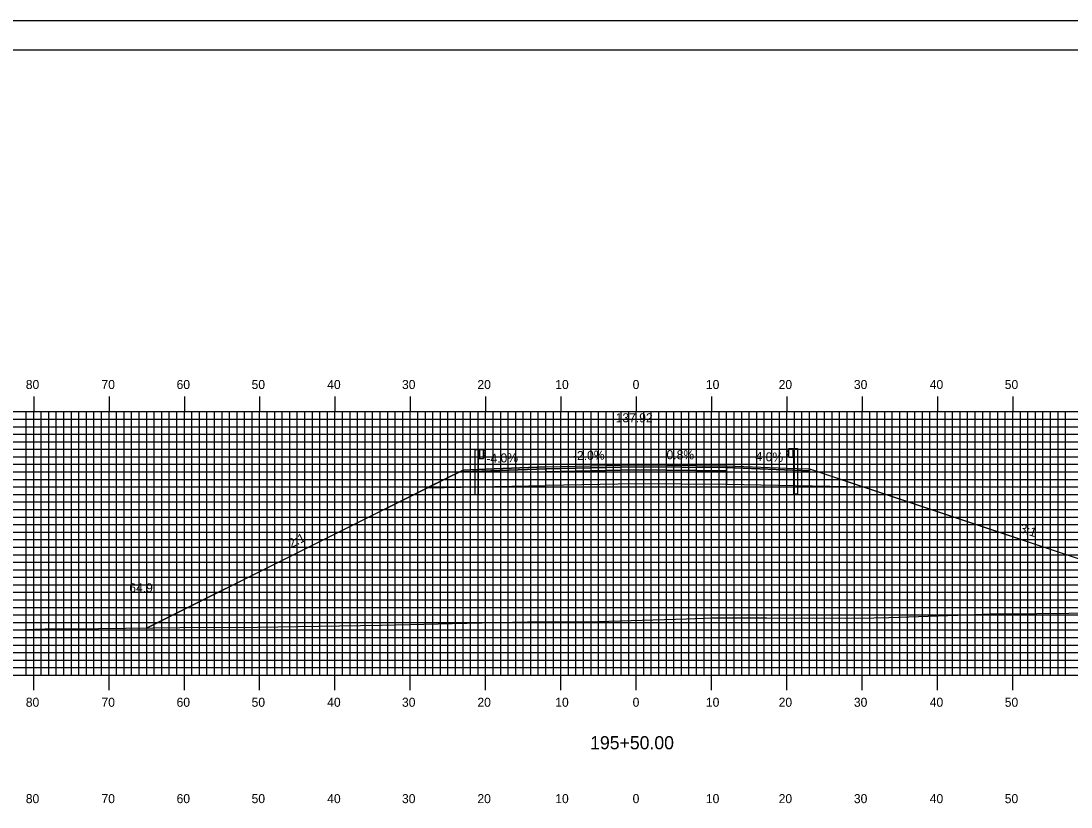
# Model space of a CAD drawing. Extents: x 1789337 to 1789680, y 442591 to 442811.
# Drawn here: x 1789421 to 1789560.4, y 442706.2 to 442810.5 of the extents above; entities that cross this region are included whole.
import ezdxf

# ---------------------------------------------------------------- set-up
doc = ezdxf.new("R2010")
doc.units = 0
for name, color, linetype in [('ANNOTATION', 7, 'Continuous'), ('BORDER', 7, 'Continuous'), ('D_Guardrail_Beam_Lt', 7, 'Continuous'), ('D_Guardrail_Beam_Rt', 7, 'Continuous'), ('D_Roadway_Centerline', 7, 'Continuous'), ('D_Roadway_Centerline_Text', 7, 'Continuous'), ('D_Roadway_Edge_Shoulder', 7, 'Continuous'), ('D_Roadway_Edge_TW', 7, 'Continuous'), ('D_Roadway_Pavement', 7, 'Continuous'), ('D_Roadway_SlopeLines', 7, 'Continuous'), ('D_Roadway_SubGrade', 7, 'Continuous'), ('D_Text_Standard', 7, 'Continuous'), ('H_V ANNOTATION', 7, 'Continuous'), ('MAJOR', 7, 'Continuous'), ('MINOR', 7, 'Continuous'), ('PLOT BOUNDARY', 7, 'Continuous'), ('S_Roadway_Centerline', 7, 'Continuous')]:
    doc.layers.add(name, color=color, linetype=linetype)

msp = doc.modelspace()

# ---------------------------------------------------------------- linework, layer by layer
at = {"layer": 'BORDER'}
msp.add_lwpolyline([(1789353.07, 442596.67), (1789673.07, 442596.67), (1789673.07, 442806.67), (1789353.07, 442806.67)], close=True, dxfattribs=at)
at = {"layer": 'D_Guardrail_Beam_Lt'}
for p, q in [((1789481.24, 442753.61), (1789481.24, 442747.61)), ((1789481.71, 442753.61), (1789481.24, 442753.61)), ((1789482.4, 442753.61), (1789481.71, 442753.61)), ((1789481.71, 442753.61), (1789481.71, 442752.44)), ((1789481.71, 442752.44), (1789482.4, 442752.44)), ((1789481.73, 442747.61), (1789481.73, 442752.44)), ((1789481.77, 442753.61), (1789481.77, 442752.44)), ((1789481.88, 442753.61), (1789481.88, 442752.44)), ((1789482.4, 442752.44), (1789482.4, 442753.61)), ((1789482.4, 442753.52), (1789482.47, 442753.51)), ((1789482.4, 442753.06), (1789482.4, 442752.99)), ((1789482.47, 442752.54), (1789482.4, 442752.52)), ((1789482.63, 442753.26), (1789482.44, 442753.12)), ((1789482.44, 442752.92), (1789482.63, 442752.79)), ((1789482.49, 442753.5), (1789482.63, 442753.4)), ((1789482.63, 442752.64), (1789482.49, 442752.54)), ((1789481.73, 442747.61), (1789481.24, 442747.61))]:
    msp.add_line(p, q, dxfattribs=at)
for centre, major_axis, start_param, end_param in [((1789482.48, 442753.06), (-0.0789, 0), 5.323254, 6.283185), ((1789482.48, 442752.99), (-0.0789, 0), 6.283185, 7.243116), ((1789482.46, 442753.47), (0.0417, 0), 0.959931, 1.376053), ((1789482.46, 442752.58), (0.0417, 0), 4.907132, 5.323254), ((1789482.58, 442753.33), (0.0877, 0), 5.323254, 7.243116), ((1789482.58, 442752.72), (0.0877, 0), 5.323254, 7.243116)]:
    msp.add_ellipse(centre, major_axis=major_axis, ratio=0.995501, start_param=start_param, end_param=end_param, dxfattribs=at)
at = {"layer": 'D_Guardrail_Beam_Rt'}
for p, q in [((1789522.85, 442753.65), (1789522.71, 442753.55)), ((1789522.71, 442753.4), (1789522.9, 442753.27)), ((1789522.9, 442753.07), (1789522.71, 442752.93)), ((1789522.71, 442752.79), (1789522.85, 442752.69)), ((1789522.94, 442753.67), (1789522.87, 442753.65)), ((1789522.87, 442752.68), (1789522.94, 442752.67)), ((1789522.94, 442753.75), (1789523.63, 442753.75)), ((1789522.94, 442752.59), (1789522.94, 442753.75)), ((1789522.94, 442753.2), (1789522.94, 442753.13)), ((1789523.63, 442752.59), (1789522.94, 442752.59)), ((1789523.46, 442753.75), (1789523.46, 442752.59)), ((1789523.57, 442753.75), (1789523.57, 442752.59)), ((1789523.61, 442747.75), (1789523.61, 442752.59)), ((1789523.63, 442753.75), (1789524.1, 442753.75)), ((1789523.63, 442753.75), (1789523.63, 442752.59)), ((1789524.1, 442753.75), (1789524.1, 442747.75)), ((1789523.61, 442747.75), (1789524.1, 442747.75))]:
    msp.add_line(p, q, dxfattribs=at)
for centre, major_axis, start_param, end_param in [((1789522.76, 442753.48), (-0.0877, 0), 5.323254, 7.243116), ((1789522.76, 442752.86), (-0.0877, 0), 5.323254, 7.243116), ((1789522.87, 442753.61), (-0.0417, 0), 4.907132, 5.323254), ((1789522.87, 442752.72), (-0.0417, 0), 0.959931, 1.376053), ((1789522.86, 442753.2), (0.0789, 0), 0, 0.959931), ((1789522.86, 442753.13), (0.0789, 0), 5.323254, 6.283185)]:
    msp.add_ellipse(centre, major_axis=major_axis, ratio=0.995501, start_param=start_param, end_param=end_param, dxfattribs=at)
at = {"layer": 'D_Roadway_Centerline'}
msp.add_lwpolyline([(1789437.75, 442729.94), (1789474.92, 442748.53), (1789479.67, 442750.9), (1789482.67, 442751.02), (1789490.67, 442751.34), (1789502.67, 442751.58), (1789514.67, 442751.49), (1789522.67, 442751.17), (1789525.67, 442751.05), (1789532.95, 442748.62), (1789582.06, 442732.25)], dxfattribs=at)
at = {"layer": 'D_Roadway_Edge_Shoulder'}
for points in [[(1789490.67, 442751.34), (1789482.67, 442751.02), (1789482.67, 442751.02), (1789479.67, 442750.9), (1789479.67, 442750.65), (1789490.67, 442751.09)], [(1789514.67, 442751.49), (1789522.67, 442751.17), (1789522.67, 442751.17), (1789525.67, 442751.05), (1789525.67, 442750.8), (1789514.67, 442751.24)]]:
    msp.add_lwpolyline(points, close=True, dxfattribs=at)
at = {"layer": 'D_Roadway_Edge_TW'}
msp.add_lwpolyline([(1789490.67, 442751.09), (1789490.67, 442751.34), (1789502.67, 442751.58), (1789514.67, 442751.49), (1789514.67, 442751.24), (1789502.67, 442751.33)], close=True, dxfattribs=at)
at = {"layer": 'D_Roadway_Pavement'}
msp.add_lwpolyline([(1789490.67, 442750.68), (1789490.67, 442751.09), (1789502.67, 442751.33), (1789514.67, 442751.24), (1789514.67, 442750.82), (1789502.67, 442750.92)], close=True, dxfattribs=at)
for points in [[(1789490.67, 442751.09), (1789490.67, 442750.68)], [(1789514.67, 442751.24), (1789514.67, 442750.82)]]:
    msp.add_lwpolyline(points, dxfattribs=at)
at = {"layer": 'D_Roadway_SlopeLines'}
for points in [[(1789525.67, 442751.05), (1789582.06, 442732.25)], [(1789479.67, 442750.9), (1789437.75, 442729.94)]]:
    msp.add_lwpolyline(points, dxfattribs=at)
at = {"layer": 'D_Roadway_SubGrade'}
for points in [[(1789490.67, 442750.68), (1789490.67, 442751.09), (1789479.67, 442750.65), (1789479.67, 442750.9), (1789474.92, 442748.53), (1789490.67, 442748.84)], [(1789490.67, 442748.84), (1789490.67, 442751.09), (1789490.67, 442750.68), (1789502.67, 442750.92), (1789514.67, 442750.82), (1789514.67, 442751.24), (1789514.67, 442748.99), (1789502.67, 442749.08)], [(1789514.67, 442750.82), (1789514.67, 442751.24), (1789525.67, 442750.8), (1789525.67, 442751.05), (1789532.95, 442748.62), (1789514.67, 442748.99)]]:
    msp.add_lwpolyline(points, close=True, dxfattribs=at)
at = {"layer": 'MAJOR'}
for p, q in [((1789422.67, 442760.67), (1789422.67, 442758.67)), ((1789432.67, 442760.67), (1789432.67, 442758.67)), ((1789442.67, 442760.67), (1789442.67, 442758.67)), ((1789452.67, 442760.67), (1789452.67, 442758.67)), ((1789462.67, 442760.67), (1789462.67, 442758.67)), ((1789472.67, 442760.67), (1789472.67, 442758.67)), ((1789482.67, 442760.67), (1789482.67, 442758.67)), ((1789492.67, 442760.67), (1789492.67, 442758.67)), ((1789502.67, 442760.67), (1789502.67, 442758.67)), ((1789512.67, 442760.67), (1789512.67, 442758.67)), ((1789522.67, 442760.67), (1789522.67, 442758.67)), ((1789532.67, 442760.67), (1789532.67, 442758.67)), ((1789542.67, 442760.67), (1789542.67, 442758.67)), ((1789552.67, 442760.67), (1789552.67, 442758.67)), ((1789362.67, 442758.67), (1789642.67, 442758.67)), ((1789362.67, 442758.67), (1789642.67, 442758.67)), ((1789422.67, 442723.67), (1789422.67, 442758.67)), ((1789432.67, 442723.67), (1789432.67, 442758.67)), ((1789442.67, 442723.67), (1789442.67, 442758.67)), ((1789452.67, 442723.67), (1789452.67, 442758.67)), ((1789462.67, 442723.67), (1789462.67, 442758.67)), ((1789472.67, 442723.67), (1789472.67, 442758.67)), ((1789482.67, 442723.67), (1789482.67, 442758.67)), ((1789492.67, 442723.67), (1789492.67, 442758.67)), ((1789502.67, 442723.67), (1789502.67, 442758.67)), ((1789512.67, 442723.67), (1789512.67, 442758.67)), ((1789522.67, 442723.67), (1789522.67, 442758.67)), ((1789532.67, 442723.67), (1789532.67, 442758.67)), ((1789542.67, 442723.67), (1789542.67, 442758.67)), ((1789552.67, 442723.67), (1789552.67, 442758.67)), ((1789362.67, 442753.67), (1789642.67, 442753.67)), ((1789362.67, 442748.67), (1789642.67, 442748.67)), ((1789362.67, 442743.67), (1789642.67, 442743.67)), ((1789362.67, 442738.67), (1789642.67, 442738.67)), ((1789362.67, 442733.67), (1789642.67, 442733.67)), ((1789362.67, 442728.67), (1789642.67, 442728.67)), ((1789362.67, 442723.67), (1789642.67, 442723.67)), ((1789362.67, 442723.67), (1789642.67, 442723.67)), ((1789422.67, 442721.66), (1789422.67, 442723.67)), ((1789432.67, 442721.66), (1789432.67, 442723.67)), ((1789442.67, 442721.66), (1789442.67, 442723.67)), ((1789452.67, 442721.66), (1789452.67, 442723.67)), ((1789462.67, 442721.66), (1789462.67, 442723.67)), ((1789472.67, 442721.66), (1789472.67, 442723.67)), ((1789482.67, 442721.66), (1789482.67, 442723.67)), ((1789492.67, 442721.66), (1789492.67, 442723.67)), ((1789502.67, 442721.66), (1789502.67, 442723.67)), ((1789512.67, 442721.66), (1789512.67, 442723.67)), ((1789522.67, 442721.66), (1789522.67, 442723.67)), ((1789532.67, 442721.66), (1789532.67, 442723.67)), ((1789542.67, 442721.66), (1789542.67, 442723.67)), ((1789552.67, 442721.66), (1789552.67, 442723.67))]:
    msp.add_line(p, q, dxfattribs=at)
at = {"layer": 'MINOR'}
for p, q in [((1789421.67, 442723.67), (1789421.67, 442758.67)), ((1789423.67, 442723.67), (1789423.67, 442758.67)), ((1789424.67, 442723.67), (1789424.67, 442758.67)), ((1789425.67, 442723.67), (1789425.67, 442758.67)), ((1789426.67, 442723.67), (1789426.67, 442758.67)), ((1789427.67, 442723.67), (1789427.67, 442758.67)), ((1789428.67, 442723.67), (1789428.67, 442758.67)), ((1789429.67, 442723.67), (1789429.67, 442758.67)), ((1789430.67, 442723.67), (1789430.67, 442758.67)), ((1789431.67, 442723.67), (1789431.67, 442758.67)), ((1789433.67, 442723.67), (1789433.67, 442758.67)), ((1789434.67, 442723.67), (1789434.67, 442758.67)), ((1789435.67, 442723.67), (1789435.67, 442758.67)), ((1789436.67, 442723.67), (1789436.67, 442758.67)), ((1789437.67, 442723.67), (1789437.67, 442758.67)), ((1789438.67, 442723.67), (1789438.67, 442758.67)), ((1789439.67, 442723.67), (1789439.67, 442758.67)), ((1789440.67, 442723.67), (1789440.67, 442758.67)), ((1789441.67, 442723.67), (1789441.67, 442758.67)), ((1789443.67, 442723.67), (1789443.67, 442758.67)), ((1789444.67, 442723.67), (1789444.67, 442758.67)), ((1789445.67, 442723.67), (1789445.67, 442758.67)), ((1789446.67, 442723.67), (1789446.67, 442758.67)), ((1789447.67, 442723.67), (1789447.67, 442758.67)), ((1789448.67, 442723.67), (1789448.67, 442758.67)), ((1789449.67, 442723.67), (1789449.67, 442758.67)), ((1789450.67, 442723.67), (1789450.67, 442758.67)), ((1789451.67, 442723.67), (1789451.67, 442758.67)), ((1789453.67, 442723.67), (1789453.67, 442758.67)), ((1789454.67, 442723.67), (1789454.67, 442758.67)), ((1789455.67, 442723.67), (1789455.67, 442758.67)), ((1789456.67, 442723.67), (1789456.67, 442758.67)), ((1789457.67, 442723.67), (1789457.67, 442758.67)), ((1789458.67, 442723.67), (1789458.67, 442758.67)), ((1789459.67, 442723.67), (1789459.67, 442758.67)), ((1789460.67, 442723.67), (1789460.67, 442758.67)), ((1789461.67, 442723.67), (1789461.67, 442758.67)), ((1789463.67, 442723.67), (1789463.67, 442758.67)), ((1789464.67, 442723.67), (1789464.67, 442758.67)), ((1789465.67, 442723.67), (1789465.67, 442758.67)), ((1789466.67, 442723.67), (1789466.67, 442758.67)), ((1789467.67, 442723.67), (1789467.67, 442758.67)), ((1789468.67, 442723.67), (1789468.67, 442758.67)), ((1789469.67, 442723.67), (1789469.67, 442758.67)), ((1789470.67, 442723.67), (1789470.67, 442758.67)), ((1789471.67, 442723.67), (1789471.67, 442758.67)), ((1789473.67, 442723.67), (1789473.67, 442758.67)), ((1789474.67, 442723.67), (1789474.67, 442758.67)), ((1789475.67, 442723.67), (1789475.67, 442758.67)), ((1789476.67, 442723.67), (1789476.67, 442758.67)), ((1789477.67, 442723.67), (1789477.67, 442758.67)), ((1789478.67, 442723.67), (1789478.67, 442758.67)), ((1789479.67, 442723.67), (1789479.67, 442758.67)), ((1789480.67, 442723.67), (1789480.67, 442758.67)), ((1789481.67, 442723.67), (1789481.67, 442758.67)), ((1789483.67, 442723.67), (1789483.67, 442758.67)), ((1789484.67, 442723.67), (1789484.67, 442758.67)), ((1789485.67, 442723.67), (1789485.67, 442758.67)), ((1789486.67, 442723.67), (1789486.67, 442758.67)), ((1789487.67, 442723.67), (1789487.67, 442758.67)), ((1789488.67, 442723.67), (1789488.67, 442758.67)), ((1789489.67, 442723.67), (1789489.67, 442758.67)), ((1789490.67, 442723.67), (1789490.67, 442758.67)), ((1789491.67, 442723.67), (1789491.67, 442758.67)), ((1789493.67, 442723.67), (1789493.67, 442758.67)), ((1789494.67, 442723.67), (1789494.67, 442758.67)), ((1789495.67, 442723.67), (1789495.67, 442758.67)), ((1789496.67, 442723.67), (1789496.67, 442758.67)), ((1789497.67, 442723.67), (1789497.67, 442758.67)), ((1789498.67, 442723.67), (1789498.67, 442758.67)), ((1789499.67, 442723.67), (1789499.67, 442758.67)), ((1789500.67, 442723.67), (1789500.67, 442758.67)), ((1789501.67, 442723.67), (1789501.67, 442758.67)), ((1789503.67, 442723.67), (1789503.67, 442758.67)), ((1789504.67, 442723.67), (1789504.67, 442758.67)), ((1789505.67, 442723.67), (1789505.67, 442758.67)), ((1789506.67, 442723.67), (1789506.67, 442758.67)), ((1789507.67, 442723.67), (1789507.67, 442758.67)), ((1789508.67, 442723.67), (1789508.67, 442758.67)), ((1789509.67, 442723.67), (1789509.67, 442758.67)), ((1789510.67, 442723.67), (1789510.67, 442758.67)), ((1789511.67, 442723.67), (1789511.67, 442758.67)), ((1789513.67, 442723.67), (1789513.67, 442758.67)), ((1789514.67, 442723.67), (1789514.67, 442758.67)), ((1789515.67, 442723.67), (1789515.67, 442758.67)), ((1789516.67, 442723.67), (1789516.67, 442758.67)), ((1789517.67, 442723.67), (1789517.67, 442758.67)), ((1789518.67, 442723.67), (1789518.67, 442758.67)), ((1789519.67, 442723.67), (1789519.67, 442758.67)), ((1789520.67, 442723.67), (1789520.67, 442758.67)), ((1789521.67, 442723.67), (1789521.67, 442758.67)), ((1789523.67, 442723.67), (1789523.67, 442758.67)), ((1789524.67, 442723.67), (1789524.67, 442758.67)), ((1789525.67, 442723.67), (1789525.67, 442758.67)), ((1789526.67, 442723.67), (1789526.67, 442758.67)), ((1789527.67, 442723.67), (1789527.67, 442758.67)), ((1789528.67, 442723.67), (1789528.67, 442758.67)), ((1789529.67, 442723.67), (1789529.67, 442758.67)), ((1789530.67, 442723.67), (1789530.67, 442758.67)), ((1789531.67, 442723.67), (1789531.67, 442758.67)), ((1789533.67, 442723.67), (1789533.67, 442758.67)), ((1789534.67, 442723.67), (1789534.67, 442758.67)), ((1789535.67, 442723.67), (1789535.67, 442758.67)), ((1789536.67, 442723.67), (1789536.67, 442758.67)), ((1789537.67, 442723.67), (1789537.67, 442758.67)), ((1789538.67, 442723.67), (1789538.67, 442758.67)), ((1789539.67, 442723.67), (1789539.67, 442758.67)), ((1789540.67, 442723.67), (1789540.67, 442758.67)), ((1789541.67, 442723.67), (1789541.67, 442758.67)), ((1789543.67, 442723.67), (1789543.67, 442758.67)), ((1789544.67, 442723.67), (1789544.67, 442758.67)), ((1789545.67, 442723.67), (1789545.67, 442758.67)), ((1789546.67, 442723.67), (1789546.67, 442758.67)), ((1789547.67, 442723.67), (1789547.67, 442758.67)), ((1789548.67, 442723.67), (1789548.67, 442758.67)), ((1789549.67, 442723.67), (1789549.67, 442758.67)), ((1789550.67, 442723.67), (1789550.67, 442758.67)), ((1789551.67, 442723.67), (1789551.67, 442758.67)), ((1789553.67, 442723.67), (1789553.67, 442758.67)), ((1789554.67, 442723.67), (1789554.67, 442758.67)), ((1789555.67, 442723.67), (1789555.67, 442758.67)), ((1789556.67, 442723.67), (1789556.67, 442758.67)), ((1789557.67, 442723.67), (1789557.67, 442758.67)), ((1789558.67, 442723.67), (1789558.67, 442758.67)), ((1789559.67, 442723.67), (1789559.67, 442758.67)), ((1789362.67, 442757.67), (1789642.67, 442757.67)), ((1789362.67, 442756.67), (1789642.67, 442756.67)), ((1789362.67, 442755.67), (1789642.67, 442755.67)), ((1789362.67, 442754.67), (1789642.67, 442754.67)), ((1789362.67, 442752.67), (1789642.67, 442752.67)), ((1789362.67, 442751.67), (1789642.67, 442751.67)), ((1789362.67, 442750.67), (1789642.67, 442750.67)), ((1789362.67, 442749.67), (1789642.67, 442749.67)), ((1789362.67, 442747.67), (1789642.67, 442747.67)), ((1789362.67, 442746.67), (1789642.67, 442746.67)), ((1789362.67, 442745.67), (1789642.67, 442745.67)), ((1789362.67, 442744.67), (1789642.67, 442744.67)), ((1789362.67, 442742.67), (1789642.67, 442742.67)), ((1789362.67, 442741.67), (1789642.67, 442741.67)), ((1789362.67, 442740.67), (1789642.67, 442740.67)), ((1789362.67, 442739.67), (1789642.67, 442739.67)), ((1789362.67, 442737.67), (1789642.67, 442737.67)), ((1789362.67, 442736.67), (1789642.67, 442736.67)), ((1789362.67, 442735.67), (1789642.67, 442735.67)), ((1789362.67, 442734.67), (1789642.67, 442734.67)), ((1789362.67, 442732.67), (1789642.67, 442732.67)), ((1789362.67, 442731.67), (1789642.67, 442731.67)), ((1789362.67, 442730.67), (1789642.67, 442730.67)), ((1789362.67, 442729.67), (1789642.67, 442729.67)), ((1789362.67, 442727.67), (1789642.67, 442727.67)), ((1789362.67, 442726.67), (1789642.67, 442726.67)), ((1789362.67, 442725.67), (1789642.67, 442725.67)), ((1789362.67, 442724.67), (1789642.67, 442724.67))]:
    msp.add_line(p, q, dxfattribs=at)
at = {"layer": 'PLOT BOUNDARY'}
msp.add_lwpolyline([(1789336.88, 442590.55), (1789676.88, 442590.55), (1789676.88, 442810.55), (1789336.88, 442810.55)], close=True, dxfattribs=at)
at = {"layer": 'S_Roadway_Centerline'}
msp.add_lwpolyline([(1789417.41, 442729.6), (1789424.15, 442729.81), (1789431.27, 442729.88), (1789442.05, 442729.99), (1789452.37, 442730.06), (1789460.5, 442730.19), (1789468.83, 442730.3), (1789478.24, 442730.54), (1789488.22, 442730.75), (1789496.12, 442730.73), (1789509.34, 442731.15), (1789512.73, 442731.28), (1789514.6, 442731.3), (1789520, 442731.29), (1789532.23, 442731.23), (1789536.2, 442731.33), (1789545.35, 442731.65), (1789549.68, 442731.82), (1789551.48, 442731.83), (1789555.86, 442731.87), (1789568.61, 442731.98)], dxfattribs=at)

# ---------------------------------------------------------------- texts
at = {"layer": 'ANNOTATION'}
for s, rotation, p in [('-4.0%', 2.2906, (1789482.8, 442751.83)), ('-2.0%', 1.1458, (1789494.28, 442752.22)), ('0.8%', 359.5531, (1789506.69, 442752.35)), ('-4.0%', 357.7094, (1789517.96, 442752.16)), ('3:1', 341.5651, (1789553.47, 442742.69)), ('2:1', 26.5651, (1789456.86, 442740.53))]:
    msp.add_text(s, height=1.2, rotation=rotation, dxfattribs=at).set_placement(p)
at = {"layer": 'D_Roadway_Centerline'}
for s, p in [('C', (1789502.66, 442751.58)), ('L', (1789502.67, 442751.58))]:
    msp.add_text(s, height=0.0146, dxfattribs=at).set_placement(p)
at = {"layer": 'D_Roadway_Centerline_Text'}
msp.add_text('137.92', height=1.2, dxfattribs=at).set_placement((1789499.94, 442757.25))
at = {"layer": 'D_Text_Standard'}
msp.add_text("64.9'", height=1.2, dxfattribs=at).set_placement((1789435.36, 442734.67))
at = {"layer": 'H_V ANNOTATION'}
for s, height, p in [('80', 1.2, (1789421.62, 442761.67)), ('70', 1.2, (1789431.67, 442761.67)), ('60', 1.2, (1789441.64, 442761.67)), ('50', 1.2, (1789451.6, 442761.67)), ('40', 1.2, (1789461.64, 442761.67)), ('30', 1.2, (1789471.57, 442761.67)), ('20', 1.2, (1789481.58, 442761.67)), ('10', 1.2, (1789491.92, 442761.67)), ('0', 1.2, (1789502.19, 442761.67)), ('10', 1.2, (1789511.92, 442761.67)), ('20', 1.2, (1789521.58, 442761.67)), ('30', 1.2, (1789531.57, 442761.67)), ('40', 1.2, (1789541.64, 442761.67)), ('50', 1.2, (1789551.6, 442761.67)), ('80', 1.2, (1789421.62, 442719.47)), ('70', 1.2, (1789431.67, 442719.47)), ('60', 1.2, (1789441.64, 442719.47)), ('50', 1.2, (1789451.6, 442719.47)), ('40', 1.2, (1789461.64, 442719.47)), ('30', 1.2, (1789471.57, 442719.47)), ('20', 1.2, (1789481.58, 442719.47)), ('10', 1.2, (1789491.92, 442719.47)), ('0', 1.2, (1789502.19, 442719.47)), ('10', 1.2, (1789511.92, 442719.47)), ('20', 1.2, (1789521.58, 442719.47)), ('30', 1.2, (1789531.57, 442719.47)), ('40', 1.2, (1789541.64, 442719.47)), ('50', 1.2, (1789551.6, 442719.47)), ('195+50.00', 1.75, (1789496.55, 442713.82)), ('80', 1.2, (1789421.62, 442706.67)), ('70', 1.2, (1789431.67, 442706.67)), ('60', 1.2, (1789441.64, 442706.67)), ('50', 1.2, (1789451.6, 442706.67)), ('40', 1.2, (1789461.64, 442706.67)), ('30', 1.2, (1789471.57, 442706.67)), ('20', 1.2, (1789481.58, 442706.67)), ('10', 1.2, (1789491.92, 442706.67)), ('0', 1.2, (1789502.19, 442706.67)), ('10', 1.2, (1789511.92, 442706.67)), ('20', 1.2, (1789521.58, 442706.67)), ('30', 1.2, (1789531.57, 442706.67)), ('40', 1.2, (1789541.64, 442706.67)), ('50', 1.2, (1789551.6, 442706.67))]:
    msp.add_text(s, height=height, dxfattribs=at).set_placement(p)

doc.saveas('drawing.dxf')
